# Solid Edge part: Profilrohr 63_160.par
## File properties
Username: ahadarics
Dokumentum tartalom típus: 0
Author: ahadarics
Last saved by: ahadarics
Revision: 84
Sűrűség: 0,000 kg/m^3
Pontosság: 0,990
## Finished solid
Body 1: solid body, 175 faces, 519 edges, 346 vertices.
  Faces by surface: cylinder 107, plane 68
  Edges by curve: line 305, circle 214
Bounding box of the edges (mm): 70.400 x 70.400 x 214.000, from (-35.2, -35.2, -174.5) to (35.2, 35.2, 39.5).
Cylindrical faces by radius (mm): R0.1 x16, R0.2 x30, R0.5 x28, R1 x8, R3.75 x8, R4.8 x4, R6 x4, R31.5 x1, R33.8 x8
Planar faces by outward normal: +x 6, +y 6, +z 1, -x 4, -y 4, -z 1, oblique 46
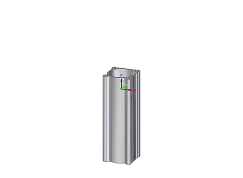
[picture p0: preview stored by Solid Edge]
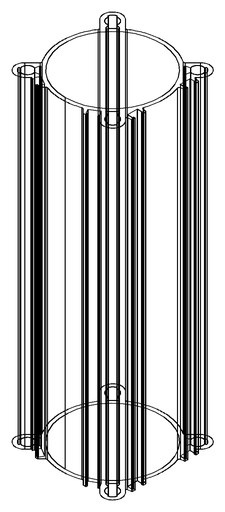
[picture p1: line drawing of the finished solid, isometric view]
